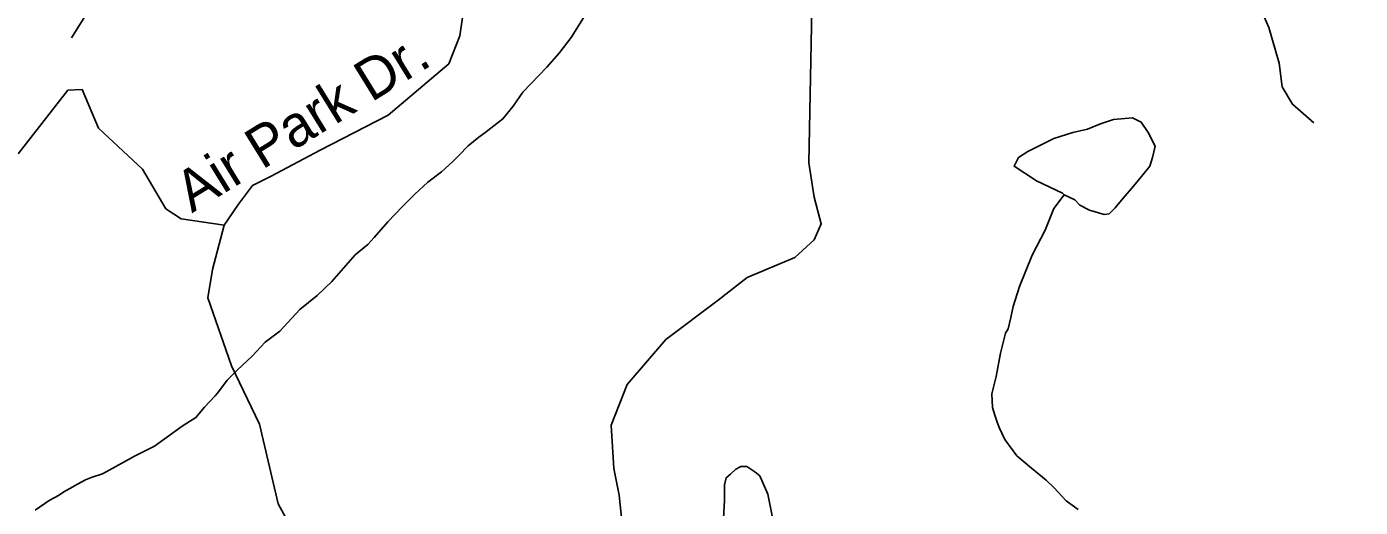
# Model space of a CAD drawing. Extents: x 2001466 to 2224147, y 644118 to 847247.
# Drawn here: x 2021734 to 2024818, y 722853 to 723965 of the extents above; entities that cross this region are included whole.
import ezdxf

# ---------------------------------------------------------------- set-up
doc = ezdxf.new("R2010")
doc.units = 0
for name, color, linetype in [('Exist Hydrographic Misc Water Feature', 7, 'Continuous'), ('Exist Road Non-System Type 51', 7, 'Continuous'), ('Exist Road Non-System Type 51 Label', 7, 'Continuous')]:
    doc.layers.add(name, color=color, linetype=linetype)

msp = doc.modelspace()

# ---------------------------------------------------------------- linework, layer by layer
at = {"layer": 'Exist Hydrographic Misc Water Feature'}
for points in [[(2023025.2, 723991.3), (2022993.2, 723939.3), (2022965.3, 723903.3), (2022937.2, 723871.3), (2022881.2, 723813.2), (2022859.3, 723781.2), (2022835.3, 723751.2), (2022793.3, 723719.2), (2022779.3, 723709.2), (2022755.3, 723689.1), (2022733.4, 723667.1), (2022719.5, 723653.2), (2022693.4, 723629.2), (2022661.4, 723605.1), (2022631.3, 723577.1), (2022603.4, 723549.1), (2022569.6, 723513.1), (2022537.6, 723477.1), (2022523.4, 723461.1), (2022493.5, 723437), (2022439.6, 723375.1), (2022405.5, 723343), (2022365.5, 723311), (2022319.6, 723260.9), (2022285.6, 723234.9), (2022255.6, 723202.9), (2022221.8, 723170.9), (2022197.8, 723146.9), (2022175.7, 723116.9), (2022169.7, 723110.9), (2022145.7, 723084.9), (2022125.6, 723060.9), (2022093.6, 723040.8), (2022057.8, 723014.8), (2022029.9, 722994.8), (2021981.9, 722970.8), (2021977.8, 722968.8), (2021909.9, 722930.8), (2021885.9, 722922.8), (2021869.9, 722916.8), (2021851.9, 722906.8), (2021833.8, 722896.8), (2021819.9, 722888.7), (2021807.8, 722880.7), (2021785.9, 722868.7), (2021753.9, 722846.7)], [(2024133.3, 723576), (2024129.2, 723580), (2024069.3, 723607.9), (2024017.2, 723641.9), (2024027.3, 723661.9), (2024049, 723675.9), (2024109.1, 723706), (2024153.2, 723720), (2024187, 723728), (2024217.2, 723740), (2024247.1, 723750), (2024273.1, 723752), (2024291.2, 723754), (2024311.1, 723744), (2024327.1, 723720.1), (2024343.1, 723688.1), (2024337.1, 723662.1), (2024331.2, 723642.1), (2024315.2, 723622.1), (2024293.2, 723596.1), (2024269.2, 723568.1), (2024251.2, 723546.1), (2024237.3, 723532.1), (2024225.2, 723530.1), (2024191.3, 723540.1), (2024169.2, 723552.1), (2024157.3, 723564.1), (2024133.3, 723576)], [(2024133.3, 723576), (2024109.3, 723544), (2024089.2, 723494), (2024059.3, 723436), (2024029.3, 723363.9), (2024015.4, 723317.9), (2024009.4, 723291.9), (2024003.3, 723265.9), (2023997.3, 723256), (2023985.5, 723209.9), (2023975.4, 723155.9), (2023965.6, 723116), (2023967.4, 723084), (2023973.6, 723063.9), (2023977.7, 723050), (2023983.4, 723036), (2023995.5, 723010), (2024023.6, 722972), (2024057.6, 722944), (2024091.7, 722916), (2024109.5, 722898), (2024137.6, 722868.1), (2024165.5, 722848.1)], [(2023345.7, 722827.6), (2023347.7, 722869.6), (2023347.7, 722905.6), (2023351.6, 722921.6), (2023361.7, 722929.7), (2023373.8, 722941.6), (2023385.7, 722947.7), (2023399.6, 722947.6), (2023417.7, 722935.7), (2023429.6, 722925.7), (2023447.8, 722883.6), (2023459.7, 722825.7)]]:
    msp.add_lwpolyline(points, dxfattribs=at)
at = {"layer": 'Exist Road Non-System Type 51'}
for points in [[(2024817.7, 725882.4), (2024771.3, 725612.9), (2024743.7, 725426), (2024713.1, 725190.1), (2024664.1, 725044.6), (2024553.9, 724873), (2024452.9, 724673.8), (2024382.4, 724539), (2024364.1, 724493.1), (2024330.4, 724395), (2024309, 724293.9), (2024309, 724235.7), (2024305.9, 724186.7), (2024302.8, 724149.9), (2024339.6, 724094.8), (2024416.1, 724076.4), (2024453.7, 724062), (2024535.5, 724048.8), (2024584.5, 724012.1), (2024605.9, 723963), (2024630.4, 723880.3), (2024636.6, 723825.2), (2024661.1, 723785.3), (2024710, 723742.4)], [(2022594.9, 722379.8), (2022716.1, 722401.4), (2022781, 722433.9), (2022808, 722466.4), (2022845.9, 722596.3), (2022878.4, 722639.6), (2022948.7, 722677.5), (2023024.5, 722715.4), (2023083.7, 722764.7), (2023110.2, 722821.9), (2023104.1, 722881.1), (2023091.9, 722943.3), (2023085.7, 723043.4), (2023122.5, 723137.3), (2023212.2, 723241.4), (2023332.9, 723332.4), (2023399.9, 723384.3), (2023510.1, 723431.2), (2023554.9, 723472.1), (2023571.3, 723508.8), (2023554.7, 723570.6), (2023542.7, 723649.7), (2023565.1, 724794.9), (2023535.9, 725722.9)], [(2021838.2, 723938.6), (2022112.8, 724378.7), (2022161.7, 724443.4), (2022237.7, 724560.6), (2022306.7, 724669.9), (2022375.7, 724779.3), (2022454.7, 724917.3), (2022545.3, 725066.9), (2022620, 725177.7), (2022706.3, 725314.3), (2022812.6, 725511.4), (2022851.8, 725622.2)], [(2022860.3, 724980.7), (2022873, 724485.3), (2022856.2, 724370.3), (2022808, 724247.1), (2022768.5, 724172.3), (2022735.9, 723943.6), (2022710.6, 723879.1), (2022570, 723760), (2022413.1, 723678.8), (2022299.4, 723619.3), (2022256.2, 723597.6), (2022223.7, 723554.3), (2022191.2, 723505.6)], [(2022191.2, 723505.6), (2022091.2, 723520), (2022056, 723543.5), (2022001.8, 723635.5), (2021900.1, 723730), (2021862.7, 723819.2), (2021829.6, 723817.7), (2021714.6, 723671)], [(2022191.2, 723505.6), (2022164.2, 723402.8), (2022153.3, 723337.8), (2022207.5, 723180.8), (2022272.4, 723045.5), (2022315.7, 722861.5), (2022407.7, 722693.7), (2022499.6, 722531.3), (2022591.6, 722390.6), (2022594.9, 722379.8)]]:
    msp.add_lwpolyline(points, dxfattribs=at)

# ---------------------------------------------------------------- texts
at = {"layer": 'Exist Road Non-System Type 51 Label'}
msp.add_text('Air Park Dr.', height=95, rotation=31.693, dxfattribs=at).set_placement((2022116.4, 723532.9))

doc.saveas('drawing.dxf')
